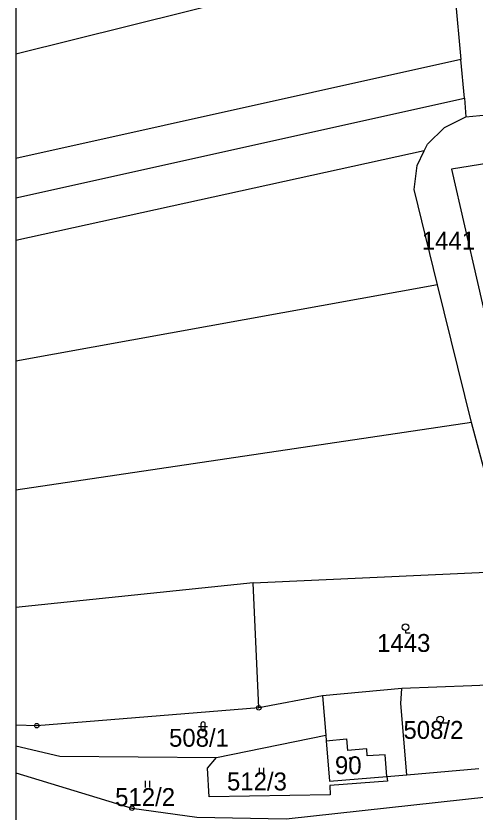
# Model space of a CAD drawing. Extents: x -564516 to -563466, y -1163913 to -1163170.
# Drawn here: x -564516.4 to -564413.8, y -1163494.9 to -1163317 of the extents above; entities that cross this region are included whole.
import ezdxf

# ---------------------------------------------------------------- set-up
doc = ezdxf.new("R2010")
doc.units = 0
for name, color, linetype in [('_parcely přehledka', 7, 'Continuous'), ('Hranice parcel', 7, 'Continuous'), ('Parcelní čísla', 7, 'Continuous'), ('Vnitřní kresba', 7, 'Continuous'), ('Značky bodu BP', 7, 'Continuous'), ('Značky budov', 7, 'Continuous'), ('Značky kultur', 7, 'Continuous')]:
    doc.layers.add(name, color=color, linetype=linetype)

msp = doc.modelspace()

# ---------------------------------------------------------------- linework, layer by layer
at = {"layer": '_parcely přehledka'}
msp.add_lwpolyline([(-564516.35, -1163170.03), (-564516.35, -1163912.53), (-563466.35, -1163912.53), (-563466.35, -1163170.03)], dxfattribs=at)
at = {"layer": 'Hranice parcel'}
for p, q in [((-564419.35, -1163301.39), (-564516.35, -1163325.53)), ((-564419.35, -1163301.39), (-564416.95, -1163326.77)), ((-564416.95, -1163326.77), (-564516.35, -1163348.86)), ((-564416.17, -1163335.4), (-564416.95, -1163326.77)), ((-564516.35, -1163357.63), (-564416.17, -1163335.4)), ((-564416.17, -1163335.4), (-564415.82, -1163339.6)), ((-564415.82, -1163339.6), (-564377.75, -1163335.67)), ((-564425.13, -1163347.17), (-564516.35, -1163367.17)), ((-564422.19, -1163377.12), (-564516.35, -1163394.15)), ((-564414.56, -1163407.85), (-564422.19, -1163377.12)), ((-564414.56, -1163407.85), (-564516.35, -1163422.99)), ((-564409.08, -1163428.48), (-564414.56, -1163407.85)), ((-564463.39, -1163443.69), (-564404.27, -1163440.99)), ((-564463.39, -1163443.69), (-564516.35, -1163449.16)), ((-564462.1, -1163471.61), (-564463.39, -1163443.69)), ((-564430.16, -1163467.25), (-564447.84, -1163468.92)), ((-564447.84, -1163468.92), (-564462.1, -1163471.61)), ((-564447.84, -1163468.92), (-564447.1, -1163477.73)), ((-564471.55, -1163482.67), (-564447.1, -1163477.73)), ((-564433.46, -1163486.96), (-564429, -1163486.59)), ((-564429, -1163486.59), (-564412.93, -1163485.19))]:
    msp.add_line(p, q, dxfattribs=at)
for points in [[(-564425.13, -1163347.17), (-564424.39, -1163345.69), (-564420.62, -1163341.92), (-564415.82, -1163339.6)], [(-564422.19, -1163377.12), (-564427.41, -1163355.81), (-564426.73, -1163350.46), (-564425.13, -1163347.17)], [(-564375.89, -1163347.26), (-564386.66, -1163348.36), (-564392.67, -1163348.57), (-564397.72, -1163348.74), (-564404.66, -1163348.94), (-564419.03, -1163351.27), (-564410.33, -1163389.23), (-564409.72, -1163391.93), (-564407.26, -1163410.87)], [(-564407.43, -1163466.4), (-564414.53, -1163466.68), (-564430.16, -1163467.25)], [(-564429, -1163486.59), (-564430.34, -1163470.65), (-564430.16, -1163467.25)], [(-564462.1, -1163471.61), (-564511.7, -1163475.6), (-564516.35, -1163475.51)], [(-564447.1, -1163477.73), (-564447.06, -1163478.94), (-564446.3, -1163487.97), (-564433.46, -1163486.96)], [(-564516.35, -1163480.12), (-564506.52, -1163482.39), (-564471.55, -1163482.67)], [(-564473.17, -1163491.46), (-564473.52, -1163485.07), (-564471.55, -1163482.67)], [(-564516.35, -1163486.11), (-564490.44, -1163494.01), (-564475.97, -1163496.01), (-564456, -1163496.4), (-564405.08, -1163490.85)], [(-564433.46, -1163486.96), (-564433.38, -1163487.96), (-564446.26, -1163488.97), (-564446.18, -1163491.05), (-564473.17, -1163491.46)]]:
    msp.add_lwpolyline(points, dxfattribs=at)
at = {"layer": 'Vnitřní kresba'}
for p, q in [((-564447.06, -1163478.94), (-564442.47, -1163478.55)), ((-564442.47, -1163478.55), (-564442.26, -1163481.11)), ((-564437.98, -1163480.75), (-564442.26, -1163481.11)), ((-564437.85, -1163482.34), (-564437.98, -1163480.75)), ((-564433.84, -1163482.09), (-564437.85, -1163482.34)), ((-564433.46, -1163486.96), (-564433.84, -1163482.09))]:
    msp.add_line(p, q, dxfattribs=at)
at = {"layer": 'Značky bodu BP'}
for centre, radius in [((-564462.1, -1163471.61), 0.5), ((-564462.1, -1163471.61), 0.0303), ((-564511.7, -1163475.6), 0.5), ((-564511.7, -1163475.6), 0.0303), ((-564490.44, -1163494.01), 0.5), ((-564490.44, -1163494.01), 0.0303)]:
    msp.add_circle(centre, radius, dxfattribs=at)
at = {"layer": 'Značky budov'}
msp.add_circle((-564441.67, -1163482.89), 0.175, dxfattribs=at)
at = {"layer": 'Značky kultur'}
for p, q in [((-564429.31, -1163454.34), (-564429.31, -1163454.84)), ((-564429.31, -1163454.84), (-564428.31, -1163454.84)), ((-564475.54, -1163475.75), (-564473.54, -1163475.75)), ((-564475.04, -1163475.25), (-564475.04, -1163476.25)), ((-564474.04, -1163476.25), (-564474.04, -1163475.25)), ((-564421.59, -1163474.98), (-564419.84, -1163474.98)), ((-564461.96, -1163486.5), (-564461.96, -1163485)), ((-564460.96, -1163486.5), (-564460.96, -1163485)), ((-564487.44, -1163489.39), (-564487.44, -1163487.89)), ((-564486.44, -1163489.39), (-564486.44, -1163487.89))]:
    msp.add_line(p, q, dxfattribs=at)
for centre in [(-564429.31, -1163453.59), (-564421.59, -1163474.23)]:
    msp.add_circle(centre, 0.75, dxfattribs=at)
for centre, start, end in [((-564474.54, -1163475.25), 0, 180), ((-564474.54, -1163476.25), 180, 359.9879)]:
    msp.add_arc(centre, 0.5, start, end, dxfattribs=at)

# ---------------------------------------------------------------- texts
at = {"layer": 'Parcelní čísla'}
for s, p in [('1441', (-564425.69, -1163369.25)), ('1443', (-564435.66, -1163459.11)), ('508/2', (-564429.78, -1163478.53)), ('508/1', (-564482.15, -1163480.3)), ('90', (-564445.08, -1163486.44)), ('512/3', (-564469.2, -1163490.05)), ('512/2', (-564494.19, -1163493.54))]:
    msp.add_text(s, height=4, dxfattribs=at).set_placement(p)

doc.saveas('drawing.dxf')
